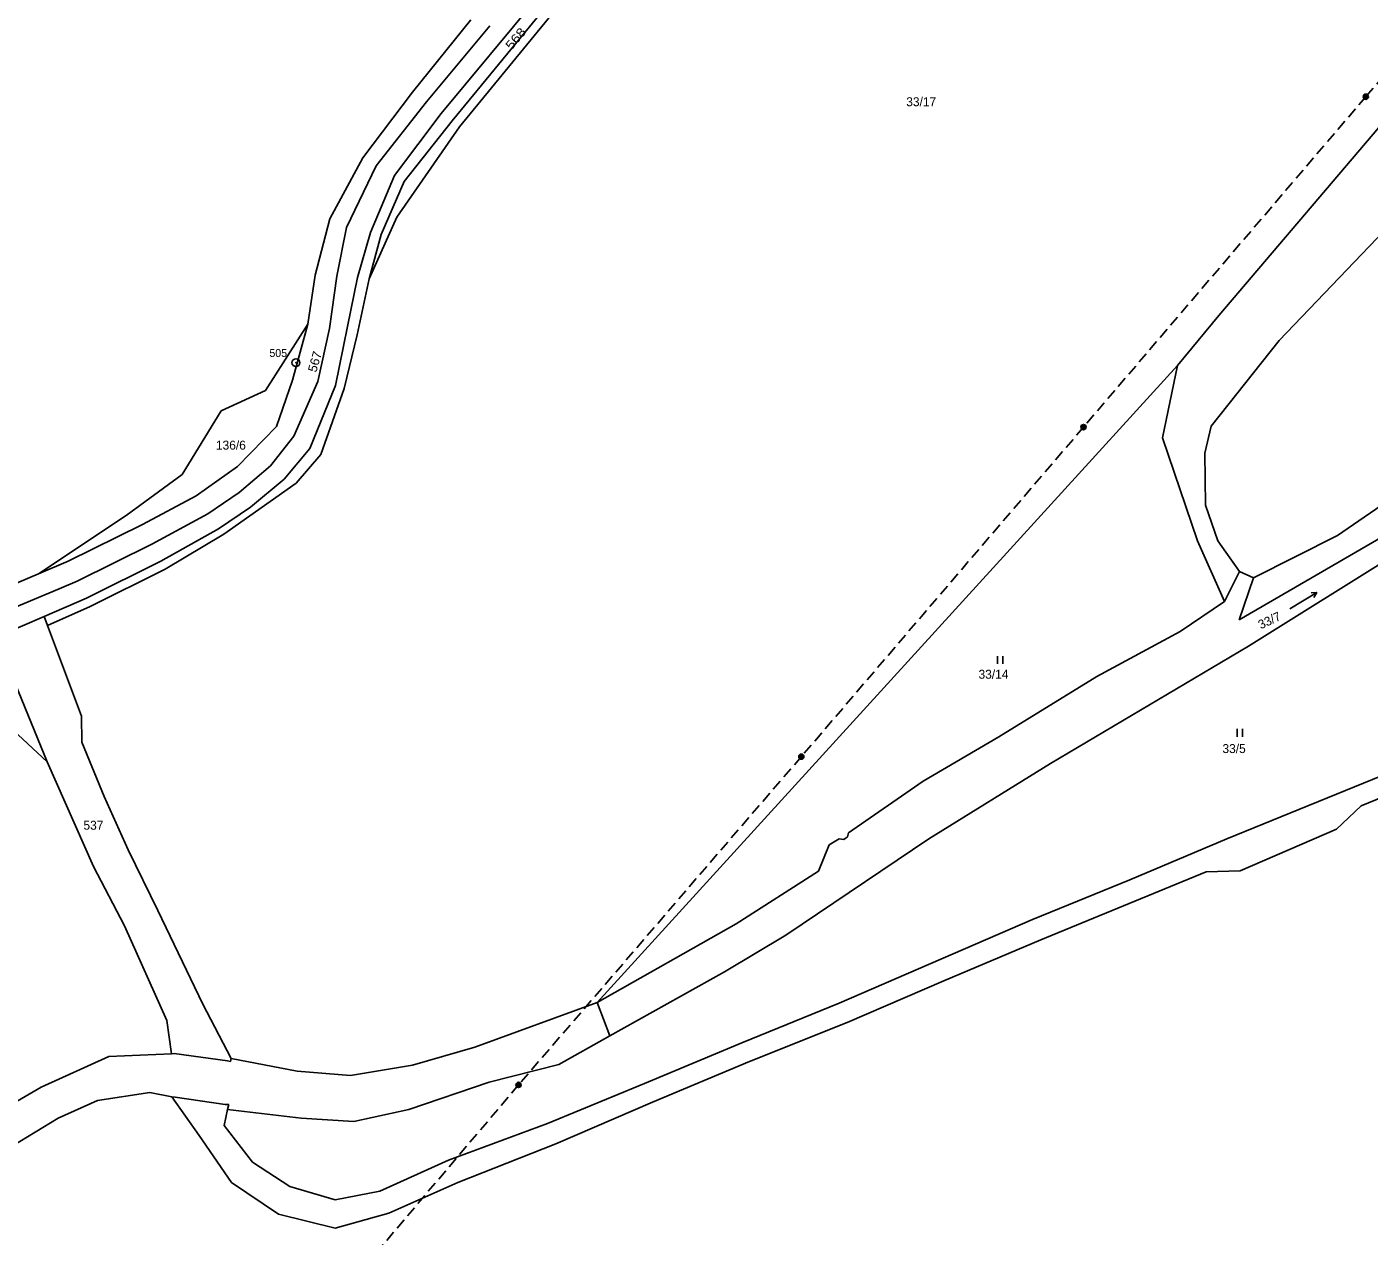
# Model space of a CAD drawing. Extents: x -885985 to -883535, y -1030025 to -1027941.
# Drawn here: x -884995.2 to -884740.1, y -1028850.6 to -1028620.8 of the extents above; entities that cross this region are included whole.
import ezdxf
from ezdxf.enums import TextEntityAlignment as Align

# ---------------------------------------------------------------- set-up
doc = ezdxf.new("R2010")
doc.units = 0
doc.header["$LTSCALE"] = 0.68
doc.linetypes.add('MEDIUM_DASHED', pattern=[4.5, 3, -1.5])
for name, color, linetype, lineweight in [('1', 7, 'Continuous', 25), ('3', 7, 'Continuous', 25), ('6', 7, 'Continuous', 25), ('8', 7, 'Continuous', 25)]:
    doc.layers.add(name, color=color, linetype=linetype, lineweight=lineweight)
doc.layers.add('2', color=7, linetype='Continuous')

msp = doc.modelspace()

# ---------------------------------------------------------------- linework, layer by layer
at = {"layer": '1'}
for p, q in [((-884916.48, -1028637.22), (-884890.29, -1028605.73)), ((-884912.96, -1028639.75), (-884885.14, -1028605.75)), ((-884890.45, -1028609.52), (-884914.37, -1028638.65)), ((-884921.91, -1028633.2), (-884910.84, -1028619.42)), ((-884907.24, -1028620.55), (-884919.27, -1028635.04)), ((-884931.34, -1028645.63), (-884921.91, -1028633.2)), ((-884919.27, -1028635.04), (-884928.8, -1028647.19)), ((-884925.3, -1028649.02), (-884916.48, -1028637.22)), ((-884924.87, -1028656.93), (-884912.96, -1028639.75)), ((-884914.37, -1028638.65), (-884923.47, -1028650.13)), ((-884738.26, -1028639.89), (-884768.69, -1028675.6)), ((-884937.63, -1028657.26), (-884931.34, -1028645.63)), ((-884928.8, -1028647.19), (-884934.42, -1028658.9)), ((-884929.86, -1028659.88), (-884925.3, -1028649.02)), ((-884923.47, -1028650.13), (-884927.88, -1028660.21)), ((-884757.19, -1028680.37), (-884728.36, -1028650.17)), ((-884940.41, -1028667.94), (-884937.63, -1028657.26)), ((-884930.16, -1028668.68), (-884924.87, -1028656.93)), ((-884934.42, -1028658.9), (-884936.28, -1028668.18)), ((-884932.37, -1028668.38), (-884929.86, -1028659.88)), ((-884927.88, -1028660.21), (-884930.16, -1028668.68)), ((-884941.8, -1028677.26), (-884940.41, -1028667.94)), ((-884936.28, -1028668.18), (-884937.67, -1028678.1)), ((-884934.24, -1028677.73), (-884932.37, -1028668.38)), ((-884932.43, -1028679.31), (-884930.16, -1028668.68)), ((-884768.69, -1028675.6), (-884776.53, -1028685.15)), ((-884949.87, -1028689.91), (-884941.8, -1028677.26)), ((-884944.72, -1028687.9), (-884941.8, -1028677.26)), ((-884937.67, -1028678.1), (-884939.92, -1028688.15)), ((-884936.55, -1028688.92), (-884934.24, -1028677.73)), ((-884934.87, -1028689.49), (-884932.43, -1028679.31)), ((-884770.12, -1028696.64), (-884757.19, -1028680.37)), ((-884886.82, -1028806.2), (-884776.53, -1028685.15)), ((-884776.53, -1028685.15), (-884779.38, -1028698.9)), ((-884947.74, -1028696.7), (-884944.72, -1028687.9)), ((-884939.92, -1028688.15), (-884944.48, -1028698.56)), ((-884941.42, -1028700.88), (-884936.55, -1028688.92)), ((-884958.25, -1028693.76), (-884949.87, -1028689.91)), ((-884939.31, -1028702.07), (-884934.87, -1028689.49)), ((-884965.66, -1028705.83), (-884958.25, -1028693.76)), ((-884771.33, -1028701.8), (-884770.12, -1028696.64)), ((-884955.16, -1028704.31), (-884947.74, -1028696.7)), ((-884944.48, -1028698.56), (-884948.9, -1028704.2)), ((-884779.38, -1028698.9), (-884772.74, -1028718.45)), ((-884946.28, -1028706.72), (-884941.42, -1028700.88)), ((-884948.9, -1028704.2), (-884954.84, -1028709.28)), ((-884944.04, -1028707.5), (-884939.31, -1028702.07)), ((-884771.22, -1028711.65), (-884771.33, -1028701.8)), ((-884976.32, -1028713.61), (-884965.66, -1028705.83)), ((-884962.99, -1028709.89), (-884955.16, -1028704.31)), ((-884952.72, -1028712.08), (-884946.28, -1028706.72)), ((-884954.84, -1028709.28), (-884960.82, -1028713.34)), ((-884957.77, -1028717.19), (-884944.04, -1028707.5)), ((-884973.21, -1028715.32), (-884962.99, -1028709.89)), ((-884768.84, -1028718.48), (-884771.22, -1028711.65)), ((-884734.79, -1028709.66), (-884746.13, -1028717.41)), ((-884993.01, -1028724.72), (-884976.32, -1028713.61)), ((-884960.82, -1028713.34), (-884971.44, -1028719.06)), ((-884958.79, -1028716.19), (-884952.72, -1028712.08)), ((-884987.35, -1028722.33), (-884973.21, -1028715.32)), ((-884969.74, -1028722.34), (-884958.79, -1028716.19)), ((-884734.34, -1028715.78), (-884764.82, -1028733.47)), ((-884971.44, -1028719.06), (-884985.65, -1028726.13)), ((-884968.91, -1028723.82), (-884957.77, -1028717.19)), ((-884772.74, -1028718.45), (-884767.57, -1028729.98)), ((-884764.76, -1028724.31), (-884768.84, -1028718.48)), ((-884746.13, -1028717.41), (-884762.08, -1028725.47)), ((-884763.06, -1028738.5), (-884733.63, -1028720.09)), ((-884993.01, -1028724.72), (-884987.35, -1028722.33)), ((-884983.89, -1028729.34), (-884969.74, -1028722.34)), ((-884983.15, -1028730.91), (-884968.91, -1028723.82)), ((-884764.76, -1028724.31), (-884767.57, -1028729.98)), ((-884762.08, -1028725.47), (-884764.76, -1028724.31)), ((-885002.27, -1028728.64), (-884993.01, -1028724.72)), ((-884985.65, -1028726.13), (-884989.08, -1028727.59)), ((-884764.82, -1028733.47), (-884762.08, -1028725.47)), ((-884989.08, -1028727.59), (-884998.46, -1028731.48)), ((-884991.94, -1028732.85), (-884983.89, -1028729.34)), ((-884991.3, -1028734.57), (-884983.15, -1028730.91)), ((-884767.57, -1028729.98), (-884776.02, -1028735.69)), ((-885000.12, -1028736.41), (-884991.94, -1028732.85)), ((-884991.3, -1028734.57), (-884991.94, -1028732.85)), ((-884984.8, -1028751.79), (-884991.3, -1028734.57)), ((-884776.02, -1028735.69), (-884791.83, -1028744.23)), ((-884800.66, -1028760.78), (-884763.06, -1028738.5)), ((-884791.83, -1028744.23), (-884810.48, -1028755.71)), ((-884997.39, -1028745.58), (-884991.36, -1028760.48)), ((-884984.72, -1028756.71), (-884984.8, -1028751.79)), ((-884997.83, -1028754.45), (-884991.36, -1028760.48)), ((-884980.48, -1028767.02), (-884984.72, -1028756.71)), ((-884810.48, -1028755.71), (-884824.88, -1028764.12)), ((-884741.61, -1028768.83), (-884710.22, -1028755.77)), ((-884767.18, -1028775.08), (-884730.12, -1028760.01)), ((-884991.36, -1028760.48), (-884982.54, -1028780.34)), ((-884823.8, -1028775.11), (-884800.66, -1028760.78)), ((-884824.88, -1028764.12), (-884839.04, -1028773.96)), ((-884975.96, -1028777.21), (-884980.48, -1028767.02)), ((-884746.28, -1028773.24), (-884741.61, -1028768.83)), ((-884850.96, -1028793.39), (-884823.8, -1028775.11)), ((-884840.83, -1028775.08), (-884842.71, -1028776.23)), ((-884839.92, -1028775.22), (-884840.83, -1028775.08)), ((-884839.23, -1028774.74), (-884839.92, -1028775.22)), ((-884839.04, -1028773.96), (-884839.23, -1028774.74)), ((-884785.59, -1028782.89), (-884767.18, -1028775.08)), ((-884764.64, -1028781.17), (-884746.28, -1028773.24)), ((-884970.28, -1028788.72), (-884975.96, -1028777.21)), ((-884842.71, -1028776.23), (-884844.78, -1028781.25)), ((-884982.54, -1028780.34), (-884976.67, -1028791.66)), ((-884844.78, -1028781.25), (-884860.41, -1028791.28)), ((-884804.11, -1028790.45), (-884785.59, -1028782.89)), ((-884802.51, -1028794.28), (-884771.06, -1028781.35)), ((-884771.06, -1028781.35), (-884764.64, -1028781.17)), ((-884961.77, -1028806.53), (-884970.28, -1028788.72)), ((-884840.83, -1028806.31), (-884804.11, -1028790.45)), ((-884976.67, -1028791.66), (-884968.57, -1028809.66)), ((-884860.41, -1028791.28), (-884886.82, -1028806.2)), ((-884862.6, -1028800.36), (-884850.96, -1028793.39)), ((-884820.93, -1028802.08), (-884802.51, -1028794.28)), ((-884839.28, -1028810.03), (-884820.93, -1028802.08)), ((-884910.07, -1028814.72), (-884886.82, -1028806.2)), ((-884859.35, -1028813.87), (-884840.83, -1028806.31)), ((-884956.4, -1028816.82), (-884961.77, -1028806.53)), ((-884968.57, -1028809.66), (-884967.72, -1028815.95)), ((-884857.87, -1028817.42), (-884839.28, -1028810.03)), ((-884884.39, -1028812.57), (-884894.09, -1028818.01)), ((-884877.79, -1028821.62), (-884859.35, -1028813.87)), ((-884979.64, -1028816.48), (-884992.48, -1028822.32)), ((-884967.72, -1028815.95), (-884979.64, -1028816.48)), ((-884967.72, -1028815.95), (-884967.23, -1028815.9)), ((-884967.23, -1028815.9), (-884957.09, -1028817.32)), ((-884921.89, -1028818.1), (-884910.07, -1028814.72)), ((-884957.09, -1028817.32), (-884956.5, -1028817.4)), ((-884956.5, -1028817.4), (-884956.4, -1028816.82)), ((-884956.4, -1028816.82), (-884943.84, -1028819.26)), ((-884933.72, -1028820.09), (-884921.89, -1028818.1)), ((-884894.09, -1028818.01), (-884907.32, -1028821.37)), ((-884876.31, -1028825.16), (-884857.87, -1028817.42)), ((-884943.84, -1028819.26), (-884933.72, -1028820.09)), ((-884907.32, -1028821.37), (-884922.63, -1028826.54)), ((-884896.28, -1028829.23), (-884877.79, -1028821.62)), ((-884992.48, -1028822.32), (-885007.88, -1028831.14)), ((-884981.76, -1028824.82), (-884971.82, -1028823.33)), ((-884971.82, -1028823.33), (-884967.66, -1028824.11)), ((-884967.04, -1028824.19), (-884967.66, -1028824.11)), ((-884967.66, -1028824.11), (-884962.45, -1028831.46)), ((-884957.49, -1028825.6), (-884967.04, -1028824.19)), ((-884989.27, -1028828.21), (-884981.76, -1028824.82)), ((-884957.04, -1028826.55), (-884957.69, -1028829.56)), ((-884956.83, -1028825.57), (-884957.49, -1028825.6)), ((-884957.04, -1028826.55), (-884956.83, -1028825.57)), ((-884943.05, -1028828.18), (-884957.04, -1028826.55)), ((-884922.63, -1028826.54), (-884933.03, -1028828.8)), ((-884894.69, -1028833.05), (-884876.31, -1028825.16)), ((-885004.33, -1028837.31), (-884989.27, -1028828.21)), ((-884933.03, -1028828.8), (-884943.05, -1028828.18)), ((-884915.04, -1028836.2), (-884896.28, -1028829.23)), ((-884962.45, -1028831.46), (-884956.28, -1028840.44)), ((-884957.69, -1028829.56), (-884952.34, -1028836.55)), ((-884913.28, -1028840.43), (-884894.69, -1028833.05)), ((-884952.34, -1028836.55), (-884945.19, -1028841.18)), ((-884928.13, -1028842.04), (-884915.04, -1028836.2)), ((-884956.28, -1028840.44), (-884947.4, -1028846.43)), ((-884945.19, -1028841.18), (-884936.63, -1028843.71)), ((-884936.63, -1028843.71), (-884928.13, -1028842.04)), ((-884926.38, -1028846.22), (-884913.28, -1028840.43)), ((-884947.4, -1028846.43), (-884936.59, -1028849.07)), ((-884936.59, -1028849.07), (-884926.38, -1028846.22))]:
    msp.add_line(p, q, dxfattribs=at)
msp.add_lwpolyline([(-884886.82, -1028806.2), (-884884.39, -1028812.57), (-884862.6, -1028800.36)], dxfattribs=at)
at = {"layer": '3'}
for p, q in [((-884750.049, -1028728.283), (-884750.629, -1028729.216)), ((-884810.731, -1028741.86), (-884810.731, -1028740.36)), ((-884809.73, -1028741.86), (-884809.73, -1028740.36)), ((-884765.171, -1028755.72), (-884765.171, -1028754.22)), ((-884764.17, -1028755.72), (-884764.17, -1028754.22))]:
    msp.add_line(p, q, dxfattribs=at)
msp.add_lwpolyline([(-884755.192, -1028731.374), (-884750.049, -1028728.283), (-884751.145, -1028728.357)], dxfattribs=at)
at = {"layer": '6', "linetype": 'MEDIUM_DASHED'}
for p, q in [((-884685.55, -1028569.69), (-884740.74, -1028634.04)), ((-884740.74, -1028634.04), (-884794.39, -1028696.84)), ((-884794.39, -1028696.84), (-884848.01, -1028759.48)), ((-884848.01, -1028759.48), (-884901.75, -1028821.87)), ((-884901.75, -1028821.87), (-884948.16, -1028876.61))]:
    msp.add_line(p, q, dxfattribs=at)
at = {"layer": '6'}
for centre, radius in [((-884740.7434, -1028634.0399), 0.5), ((-884740.7434, -1028634.0399), 0.4), ((-884740.7434, -1028634.0399), 0.3), ((-884740.7434, -1028634.0399), 0.2), ((-884740.7434, -1028634.0399), 0.1), ((-884794.3934, -1028696.8399), 0.5), ((-884794.3934, -1028696.8399), 0.4), ((-884794.3934, -1028696.8399), 0.3), ((-884794.3934, -1028696.8399), 0.2), ((-884794.3934, -1028696.8399), 0.1), ((-884848.0134, -1028759.4799), 0.5), ((-884848.0134, -1028759.4799), 0.4), ((-884848.0134, -1028759.4799), 0.3), ((-884848.0134, -1028759.4799), 0.2), ((-884848.0134, -1028759.4799), 0.1), ((-884901.7534, -1028821.8699), 0.5), ((-884901.7534, -1028821.8699), 0.4), ((-884901.7534, -1028821.8699), 0.3), ((-884901.7534, -1028821.8699), 0.2), ((-884901.7534, -1028821.8699), 0.1)]:
    msp.add_circle(centre, radius, dxfattribs=at)
at = {"layer": '8'}
for radius in [0.75, 0.03]:
    msp.add_circle((-884944.06, -1028684.5898), radius, dxfattribs=at)

# ---------------------------------------------------------------- texts
at = {"layer": '2'}
for s, rotation, width, p in [('568', 50, 1.2, (-884903.114, -1028625.283)), ('567', 74, 1.05, (-884940.201, -1028686.547))]:
    msp.add_text(s, height=1.7, rotation=rotation, dxfattribs=dict(at, width=width)).set_placement(p)
msp.add_text('33/17', height=1.7, dxfattribs=at).set_placement((-884825.23, -1028635.845), align=Align.CENTER)
for s, p in [('136/6', (-884959.27, -1028701.115)), ('33/14', (-884814.34, -1028744.665)), ('33/5', (-884767.98, -1028758.795)), ('537', (-884984.44, -1028773.365))]:
    msp.add_text(s, height=1.7, dxfattribs=at).set_placement(p)
msp.add_text('33/7', height=1.7, rotation=25, dxfattribs=at).set_placement((-884760.7, -1028735.285))
at = {"layer": '8'}
msp.add_text('505', height=1.5, dxfattribs=at).set_placement((-884945.749, -1028683.507), align=Align.RIGHT)

doc.saveas('drawing.dxf')
